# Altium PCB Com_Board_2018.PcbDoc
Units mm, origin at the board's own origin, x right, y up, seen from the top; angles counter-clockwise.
Board outline 97.2 x 100.86 mm, 2 copper layers (Top Layer, Bottom Layer), stack 1.57 mm thick; 18 components, 16 nets, 138 pads, 0 vias.
Unrouted connection lines stored in the file: 5.
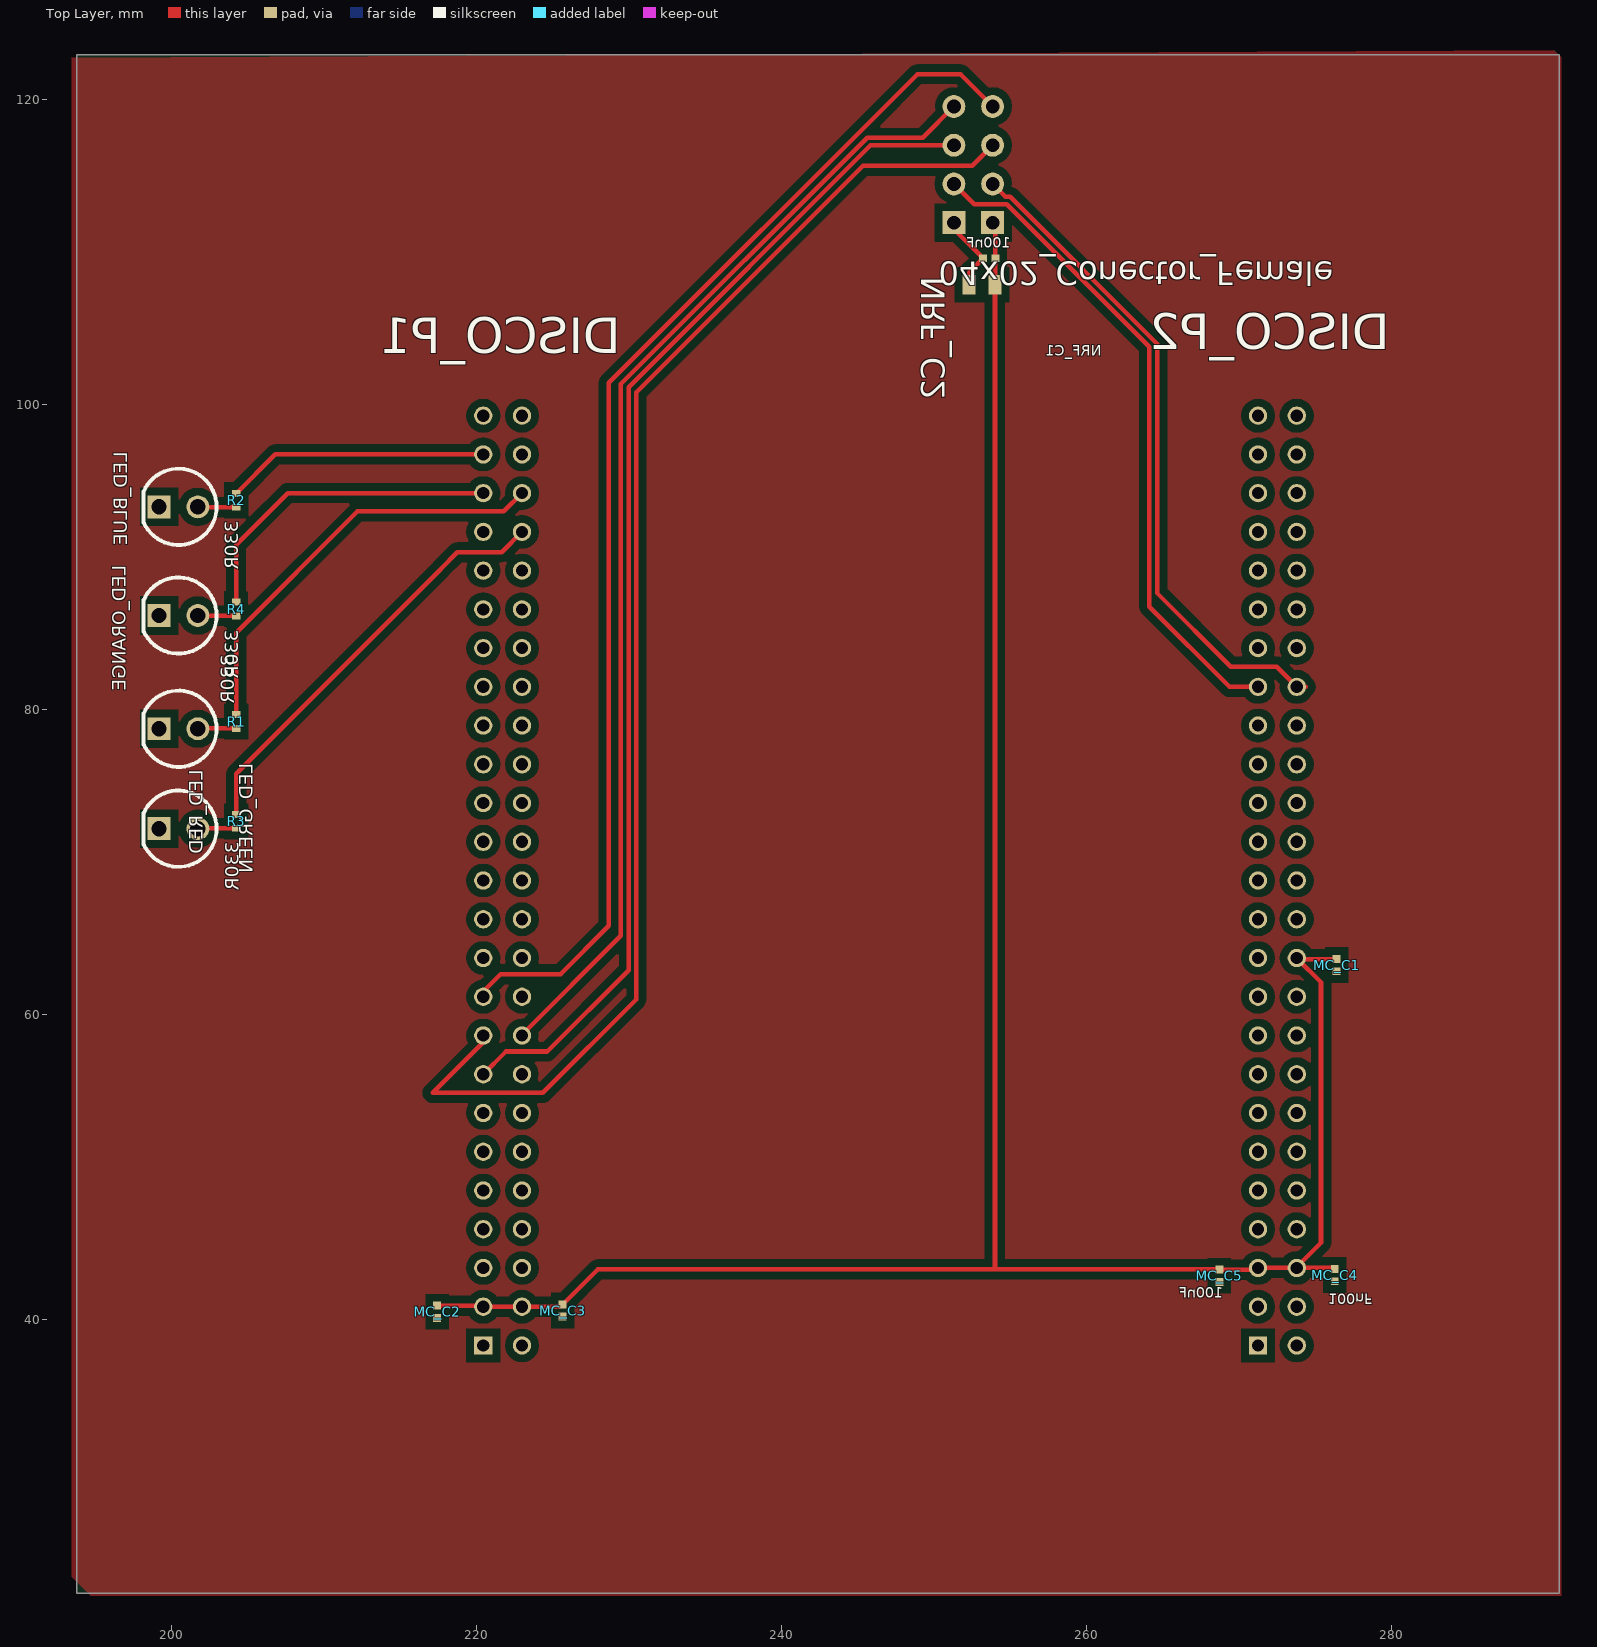
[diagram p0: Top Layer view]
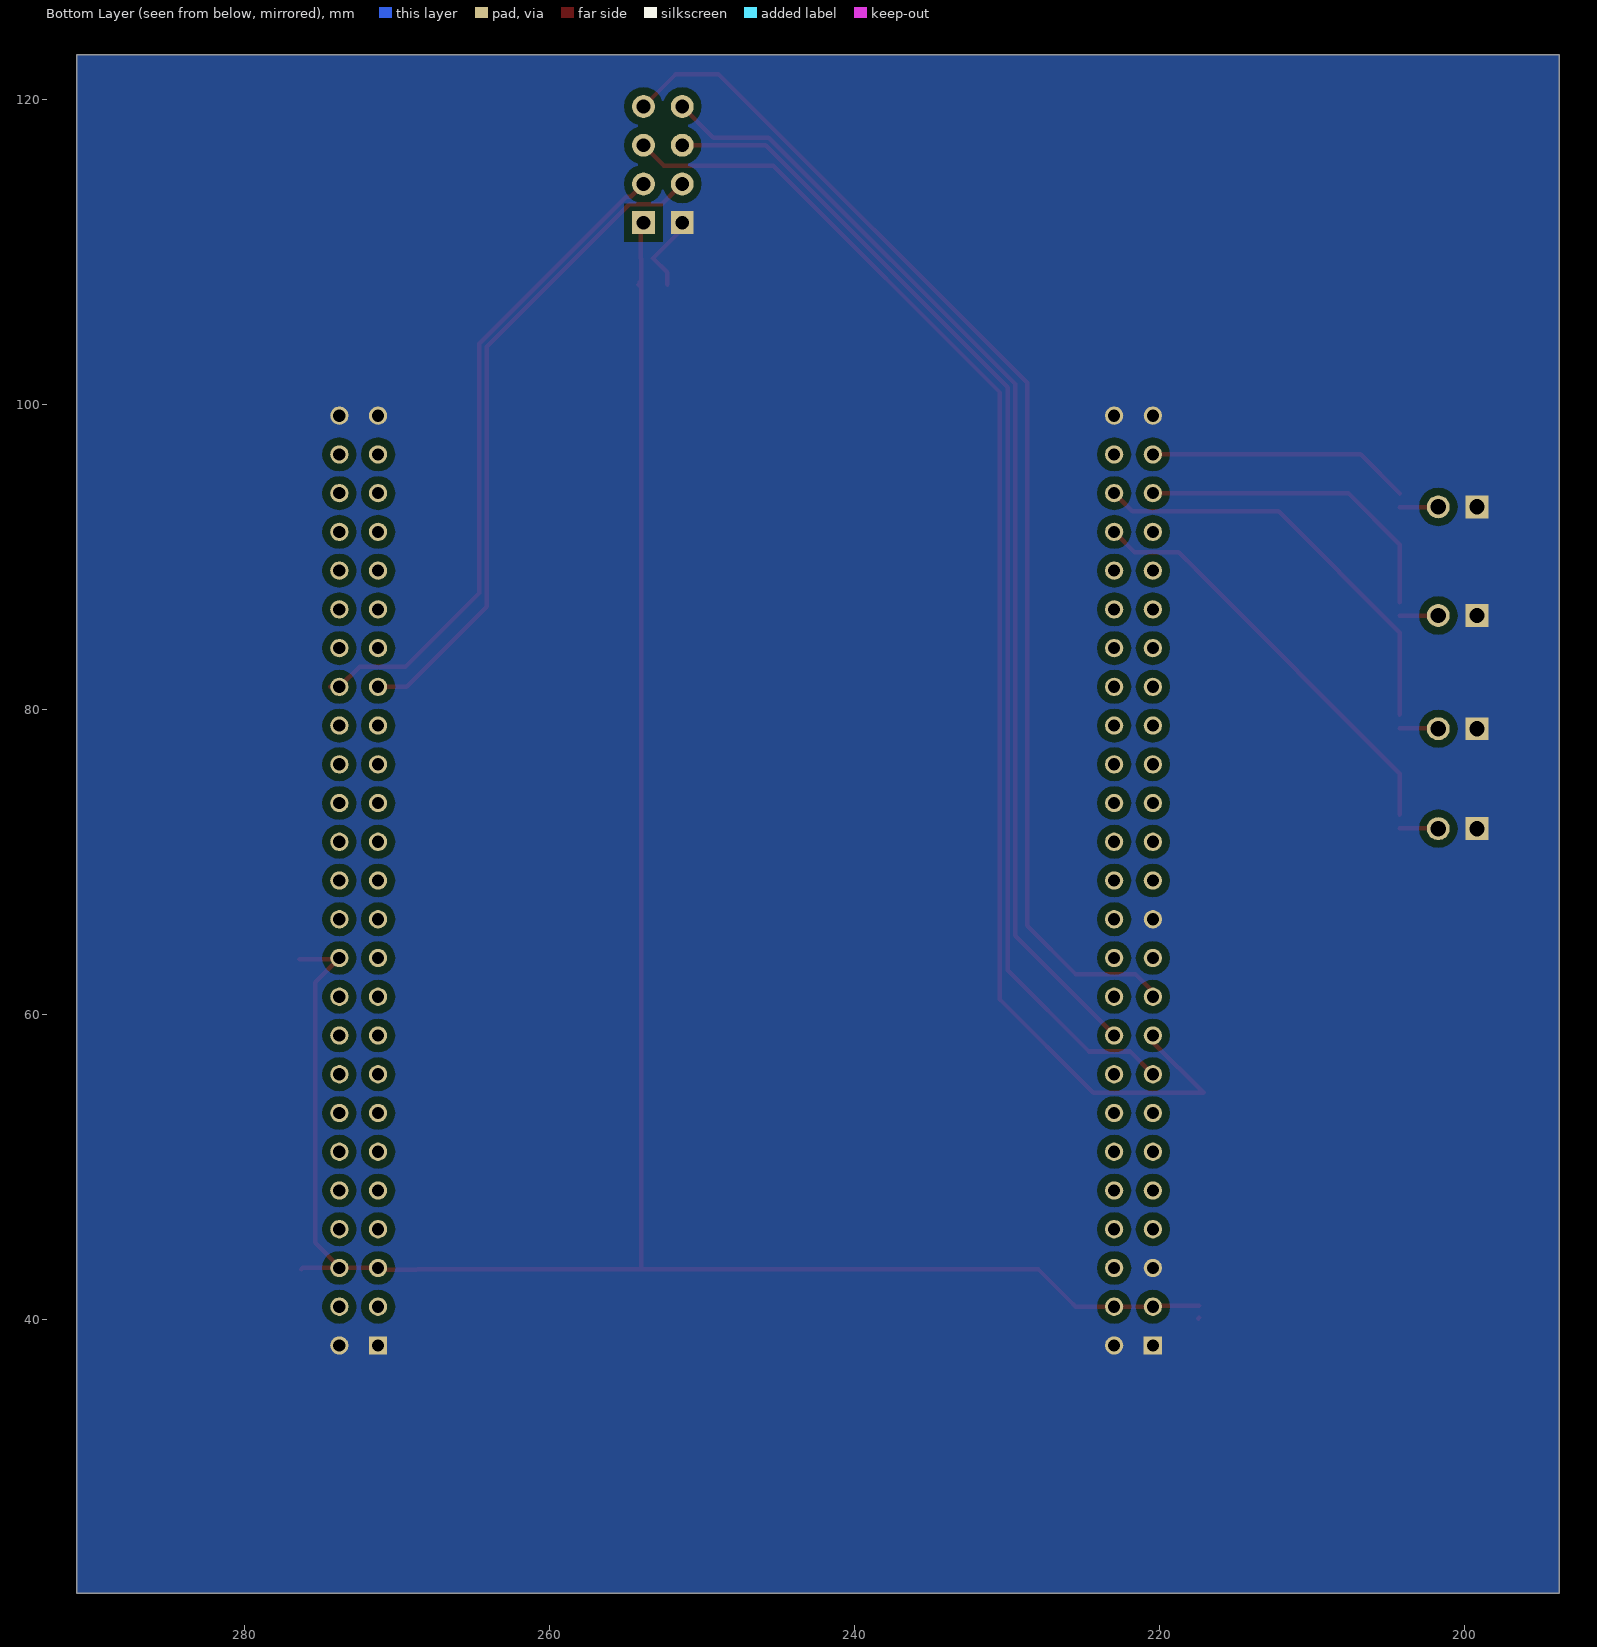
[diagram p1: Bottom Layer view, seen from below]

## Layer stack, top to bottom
Top Solder: solder mask 0.01, Solder Resist, Dk 3.5
Top Layer: signal copper 0.035
Dielectric 1: dielectric 1.5, FR-4, Dk 4.8
Bottom Layer: signal copper 0.035
Bottom Solder: solder mask 0.01, Solder Resist, Dk 3.5

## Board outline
193.775,122.937 193.775,22.075 290.975,22.075 290.975,122.937

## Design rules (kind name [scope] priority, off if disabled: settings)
Clearance Clearance_1 [All] p1: gap=0.3 ignorepadtopadclearanceinfootprint=FALSE except(0: Arc-Hole Track-Hole SMDPad-Hole THPad-Hole Via-Hole Fill-Hole Poly-Hole Region-Hole Text-Hole; 0.15: SMDPad-SMDPad; 0.2: Track-Track Track-SMDPad; 0.5: Arc-Poly Track-Poly SMDPad-Poly THPad-Poly Via-Poly Fill-Poly Poly-Poly Poly-Region Poly-Text)
HoleSize [All] p1: absolutevalues=TRUE maxlimit=10 minlimit=0.025 maxpercent=80.000 minpercent=20.000
MinimumSolderMaskSliver [All] p1 off: minsoldermaskwidth=0.2
PlaneConnect [All] p1: planeconnectstyle=Direct reliefexpansion=0.508 reliefentries=4 reliefconductorwidth=0.254 reliefairgap=0.254
PolygonConnect PolygonConnect_3 [InNet('GND')] p1: connectstyle=Direct reliefconductorwidth=0.254 reliefentries=4 polygonreliefangle="90 Angle" airgapwidth=0.254
PolygonConnect PolygonConnect_1 [InNetClass('DIRECT')] p2: connectstyle=Direct reliefconductorwidth=0.508 reliefentries=4 polygonreliefangle="90 Angle" airgapwidth=0.254
PolygonConnect PolygonConnect_2 [IsVia] p3: connectstyle=Direct reliefconductorwidth=0.254 reliefentries=4 polygonreliefangle="90 Angle" airgapwidth=0.254
PolygonConnect [All] p4: connectstyle=Direct reliefconductorwidth=0.3 reliefentries=4 polygonreliefangle="90 Angle" airgapwidth=0.254
RoutingVias [All] p1: holewidth=0.7 width=1 viastyle="Through Hole" minholewidth=0.5 minwidth=0.7 maxholewidth=6 maxwidth=6
SilkToSilkClearance [All] p1 off: silktosilkclearance=0.254
SilkToSolderMaskClearance [IsPad] p1 off: minsilkscreentomaskgap=0.254 clearancetoexposedcopper=TRUE
SolderMaskExpansion [All] p1: expansion=0.102
Width [All] p1: maxlimit=1.016 minlimit=0.2 preferedwidth=0.3
25 further rules are at their usual default settings.

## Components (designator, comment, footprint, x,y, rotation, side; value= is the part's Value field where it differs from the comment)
04x02_Conector_Female "PPPC042LFBN-RC" 04x02_Conector_Female 252.55,115.742 r270 top
DISCO_P1 "SFH11-PBPC-D25-ST-BK" 25x02_Conector_Female#1 221.693,68.799 r90 top locked
DISCO_P2 "SFH11-PBPC-D25-ST-BK" 25x02_Conector_Female#2 272.493,68.799 r90 top locked
LED_BLUE "LED" LED-5MM-PCB 200.44,93.3 r180 top
LED_GREEN "LED" LED-5MM-PCB 200.44,72.2 r180 top
LED_ORANGE "LED" LED-5MM-PCB 200.44,86.175 r180 top
LED_RED "LED" LED-5MM-PCB 200.44,78.75 r180 top
MC_C1 "100nF" 0402-CAP 276.375,63.25 r90 top value=100n
MC_C2 "100nF" 0402-CAP 217.4,40.525 r90 top value=100n
MC_C3 "100nF" 0402-CAP 225.63,40.605 r270 top value=100n
MC_C4 "100nF" 0402-CAP 276.25,42.925 r90 top value=100n
MC_C5 "100nF" 0402-CAP 268.683,42.891 r90 top value=100n
NRF_C1 "100nF" 0402-CAP 253.6,109.6 r180 top value=100n
NRF_C2 "10uF" 0805-CAP 253.125,107.867 r180 top
R1 "330R" 0402-RES-HD 204.225,79.225 r270 top value=330
R2 "330R" 0402-RES-HD 204.225,93.725 r270 top value=330
R3 "330R" 0402-RES-HD 204.225,72.675 r270 top value=330
R4 "330R" 0402-RES-HD 204.225,86.6 r270 top value=330

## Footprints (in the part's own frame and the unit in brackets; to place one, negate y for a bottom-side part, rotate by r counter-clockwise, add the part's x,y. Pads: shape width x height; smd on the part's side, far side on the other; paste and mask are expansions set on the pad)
04x02_Conector_Female [mm] "PPPC042LFBN-RC"
  round 1.5 hole 0.9: 0(-3.81,-1.27) 1(-1.27,-1.27) 2(1.27,-1.27) 4(-3.81,1.27) 5(-1.27,1.27) 6(1.27,1.27)
  rect 1.5x1.5 hole 0.9: 3(3.81,-1.27) 7(3.81,1.27)
  body extent -5.3,-2.53 5.36,2.55, height 150.38
25x02_Conector_Female#1 [mil] "SFH11-PBPC-D25-ST-BK"
  rect 47.25x47.25 hole 31.5: 1(-1200,50)
  round 47.25 hole 31.5: 2(-1200,-50) 3(-1100,50) 4(-1100,-50) 5(-1000,50) 6(-1000,-50) 7(-900,50) 8(-900,-50) 9(-800,50) 10(-800,-50) 11(-700,50) 12(-700,-50) 13(-600,50) 14(-600,-50) 15(-500,50) 16(-500,-50) 17(-400,50) 18(-400,-50) 19(-300,50) 20(-300,-50) 21(-200,50) 22(-200,-50) 23(-100,50) 24(-100,-50) 26(0,-50) 27(100,50) 28(100,-50) 29(200,50) 30(200,-50) 31(300,50) 32(300,-50) 33(400,50) 34(400,-50) 35(500,50) 36(500,-50) 37(600,50) 38(600,-50) 39(700,50) 40(700,-50) 41(800,50) 42(800,-50) 43(900,50) 44(900,-50) 45(1000,50) 46(1000,-50) 47(1100,50) 48(1100,-50) 49(1200,50) 50(1200,-50)
  oval 47.25x47.24 hole 31.5: 25(0,50)
  body extent -1350,-76 1350,161, height 333
25x02_Conector_Female#2 [mil] "SFH11-PBPC-D25-ST-BK"
  rect 47.25x47.25 hole 31.5: 1(-1200,50)
  round 47.25 hole 31.5: 2(-1200,-50) 3(-1100,50) 4(-1100,-50) 5(-1000,50) 6(-1000,-50) 7(-900,50) 8(-900,-50) 9(-800,50) 10(-800,-50) 11(-700,50) 12(-700,-50) 13(-600,50) 14(-600,-50) 15(-500,50) 16(-500,-50) 17(-400,50) 18(-400,-50) 19(-300,50) 20(-300,-50) 21(-200,50) 22(-200,-50) 23(-100,50) 24(-100,-50) 25(0,50) 26(0,-50) 27(100,50) 28(100,-50) 29(200,50) 30(200,-50) 31(300,50) 32(300,-50) 33(400,50) 34(400,-50) 35(500,50) 36(500,-50) 37(600,50) 38(600,-50) 39(700,50) 40(700,-50) 41(800,50) 42(800,-50) 43(900,50) 44(900,-50) 45(1000,50) 46(1000,-50) 47(1100,50) 48(1100,-50) 49(1200,50) 50(1200,-50)
  body extent -1350,-76 1350,161, height 333
0402-CAP [mm] "Chip Capacitor, Body 1.0x0.5mm, Height 0.6mm, IPC Medium Density"
  rect 0.52x0.52 smd: 1(-0.4,0) 2(0.4,0)
  body extent -0.55,-0.3 0.55,0.3, height 0.33
0402-RES-HD [mm] "Chip Resistor, Body 1.0x0.5mm, IPC High Density"
  rect 0.45x0.55 smd: 1(-0.45,0) 2(0.45,0)
  body extent -0.52,-0.28 0.53,0.27, height 0.4
0805-CAP [mm] "Chip Resistor, Body 2.0x1.3mm, IPC High Density"
  rect 0.85x1.3 smd: 1(-0.85,0) 2(0.85,0)
  body extent -1.1,-0.68 1.1,0.67, height 0.7
LED-5MM-PCB [mm]
  rect 1.5x1.5 hole 1: 1(1.27,0)
  round 1.5 hole 1: 2(-1.27,0)
  silkscreen extent -2.5,-2.5 2.28,2.5, body extent -2.98,-3.01 2.44,3.01, height 8.59

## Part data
04x02_Conector_Female: library part 04x02_Conector_Female, "8 Position Header Connector 0.100\" (2.54mm) Through Hole Gold"
DISCO_P1 DISCO_P2: library part 25x02_Conector_Female, "50 Position Header Connector 0.100\" (2.54mm) Through Hole Gold"
LED_BLUE LED_GREEN LED_ORANGE LED_RED: library part LED-5MM-3, "LED 5MM PTH"
MC_C1 MC_C2 MC_C3 MC_C4 MC_C5 NRF_C1: library part CC0402-100nF-A.12, "CAP CER 0.1UF 10V 20% X5R 0402", Part No=VJ0402V104ZXQPBC
NRF_C2: library part CC0806-10uF-25V-1, "CAP CER 10UF 25V X5R 0805", Part No=GRM21BR61E106KA73L
R1 R2 R3 R4: library part R0402-330R-7, "RES 330 OHM 1/10W 1% 0402 SMD", Part No=ERJ-2RKF3300X

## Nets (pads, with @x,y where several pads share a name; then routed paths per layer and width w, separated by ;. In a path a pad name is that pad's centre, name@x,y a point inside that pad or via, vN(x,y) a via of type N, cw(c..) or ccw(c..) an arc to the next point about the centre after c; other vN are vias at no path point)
GND: 04x02_Conector_Female.3 DISCO_P1.1 DISCO_P1.2 DISCO_P1.5 DISCO_P1.23 DISCO_P1.49 DISCO_P1.50 DISCO_P2.1 DISCO_P2.2 DISCO_P2.49 DISCO_P2.50 LED_BLUE.1 LED_GREEN.1 LED_ORANGE.1 LED_RED.1 MC_C1.1 MC_C2.1 MC_C3.2 MC_C4.1 MC_C5.1 NRF_C1.2 NRF_C2.2 | length 5.3
  Top Layer w0.3: MC_C2.1 MC_C2.1@217.45,40.075 ; 04x02_Conector_Female.3 251.28,111.52 NRF_C1.2 252.275,108.675 NRF_C2.2
LED_B: DISCO_P1.47 R2.1 | length 17.3
  Top Layer w0.3: R2.1 206.789,96.739 DISCO_P1.47
LED_G: DISCO_P1.44 R3.1 | length 28
  Top Layer w0.3: R3.1 204.225,75.8 217.625,89.2 217.625,89.225 218.725,90.325 221.629,90.325 DISCO_P1.44
LED_O: DISCO_P1.45 R4.1 | length 21.4
  Top Layer w0.3: R4.1 204.225,90.825 207.599,94.199 DISCO_P1.45
LED_R: DISCO_P1.46 R1.1 | length 27.9
  Top Layer w0.3: R1.1 204.225,85.05 212.175,93 221.764,93 DISCO_P1.46
NetLED_BLUE_2: LED_BLUE.2 R2.2 | length 2.4
  Top Layer w0.3: LED_BLUE.2@201.81,93.275 R2.2
NetLED_GREEN_2: LED_GREEN.2 R3.2 | length 2.3
  Top Layer w0.3: LED_GREEN.2@201.96,72.225 R3.2
NetLED_ORANGE_2: LED_ORANGE.2 R4.2 | length 2.5
  Top Layer w0.3: LED_ORANGE.2@201.735,86.15 R4.2
NetLED_RED_2: LED_RED.2 R1.2 | length 2.5
  Top Layer w0.3: LED_RED.2@201.735,78.775 R1.2
NRF_CE: 04x02_Conector_Female.2 DISCO_P2.35 | length 43.6
  Top Layer w0.3: 04x02_Conector_Female.2 252.62,113.132 254.756,113.132 264.1,103.788 264.1,86.75 269.351,81.499 DISCO_P2.35
NRF_CS#: 04x02_Conector_Female.6 DISCO_P2.36 | length 43.8
  Top Layer w0.3: 04x02_Conector_Female.6 254.66,113.632 254.964,113.632 264.6,103.995 264.6,87.65 269.425,82.825 272.437,82.825 DISCO_P2.36 DISCO_P2.36@274.349,81.499
NRF_IRQ: 04x02_Conector_Female.4 DISCO_P1.19 | length 80.4
  Top Layer w0.3: DISCO_P1.19 220.423,61.523 221.568,62.668 225.493,62.668 228.65,65.825 228.65,101.425 248.875,121.65 251.722,121.65 04x02_Conector_Female.4
SPI1_MISO: 04x02_Conector_Female.0 DISCO_P1.18 | length 74.9
  Top Layer w0.3: DISCO_P1.18@223.024,58.7 DISCO_P1.18 222.963,58.688 229.45,65.175 229.45,101.357 245.605,117.512 249.24,117.512 04x02_Conector_Female.0
SPI1_MOSI: 04x02_Conector_Female.5 DISCO_P1.17 | length 91
  Top Layer w0.3: DISCO_P1.17 220.423,58.198 217.1,54.875 224.325,54.875 230.45,61 230.45,100.8 245.322,115.672 252.48,115.672 04x02_Conector_Female.5 04x02_Conector_Female.5@253.82,117.13
SPI1_SCK: 04x02_Conector_Female.1 DISCO_P1.15 | length 78.5
  Top Layer w0.3: DISCO_P1.15 221.913,57.588 224.613,57.588 229.95,62.925 229.95,101.15 245.812,117.012 04x02_Conector_Female.1
VCC: 04x02_Conector_Female.7 DISCO_P1.3 DISCO_P1.4 DISCO_P2.5 DISCO_P2.6 DISCO_P2.22 MC_C1.2 MC_C2.2 MC_C3.1 MC_C4.2 MC_C5.2 NRF_C1.1 NRF_C2.1 | length 156.2
  Top Layer w0.3: MC_C2.2 220.357,40.925 DISCO_P1.3 DISCO_P1.4 225.484,40.859 MC_C3.1 227.925,43.3 256.675,43.3 256.7,43.325 ; 04x02_Conector_Female.7@253.588,111.7 04x02_Conector_Female.7 254,111.752 NRF_C1.1 253.975,109.575 NRF_C2.1 253.975,43.325 256.7,43.325 ; NRF_C2.1@254,107.717 NRF_C2.1@254.15,107.867 ; NRF_C2.1@254,108.117 NRF_C2.1@254.075,108.042 ; DISCO_P2.22 DISCO_P2.22@273.832,63.65 ; MC_C4.2 276.176,43.399 DISCO_P2.6 ; MC_C1.2 DISCO_P2.22@273.832,63.65 ; 256.7,43.325 268.649,43.325 MC_C5.2 271.115,43.291 DISCO_P2.5 DISCO_P2.6 ; DISCO_P2.6 273.763,43.463 275.35,45.05 275.35,62.132 DISCO_P2.22@273.832,63.65
pads on no net: DISCO_P1.6 DISCO_P1.7 DISCO_P1.8 DISCO_P1.9 DISCO_P1.10 DISCO_P1.11 DISCO_P1.12 DISCO_P1.13 DISCO_P1.14 DISCO_P1.16 DISCO_P1.20 DISCO_P1.21 DISCO_P1.22 DISCO_P1.24 DISCO_P1.25 DISCO_P1.26 DISCO_P1.27 DISCO_P1.28 DISCO_P1.29 DISCO_P1.30 DISCO_P1.31 DISCO_P1.32 DISCO_P1.33 DISCO_P1.34 DISCO_P1.35 DISCO_P1.36 DISCO_P1.37 DISCO_P1.38 DISCO_P1.39 DISCO_P1.40 DISCO_P1.41 DISCO_P1.42 DISCO_P1.43 DISCO_P1.48 DISCO_P2.3 DISCO_P2.4 DISCO_P2.7 DISCO_P2.8 DISCO_P2.9 DISCO_P2.10 DISCO_P2.11 DISCO_P2.12 DISCO_P2.13 DISCO_P2.14 DISCO_P2.15 DISCO_P2.16 DISCO_P2.17 DISCO_P2.18 DISCO_P2.19 DISCO_P2.20 DISCO_P2.21 DISCO_P2.23 DISCO_P2.24 DISCO_P2.25 DISCO_P2.26 DISCO_P2.27 DISCO_P2.28 DISCO_P2.29 DISCO_P2.30 DISCO_P2.31 DISCO_P2.32 DISCO_P2.33 DISCO_P2.34 DISCO_P2.37 DISCO_P2.38 DISCO_P2.39 DISCO_P2.40 DISCO_P2.41 DISCO_P2.42 DISCO_P2.43 DISCO_P2.44 DISCO_P2.45 DISCO_P2.46 DISCO_P2.47 DISCO_P2.48

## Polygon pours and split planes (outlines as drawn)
no net on Top Layer (solid, pour order 167): 193.45,122.75 193.45,23.15 194.7,21.9 291.1,21.9 291.1,122.775 290.625,123.25
no net on Top Layer (solid, pour order 165): 193.2,122.5
no net on Top Layer "Top Layer-No Net 1" (solid, pour order 133): 320.1,155.1
GND on Bottom Layer "Top Layer-No Net2" (solid, pour order 146): 193.775,122.937 193.775,22.075 290.975,22.075 290.975,122.937

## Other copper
Top Layer:
  region: -133.25,79.25

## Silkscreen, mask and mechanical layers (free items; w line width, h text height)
Mechanical 1:
  lines w0.5: 290.975,122.22 290.975,22.075 ; 193.775,22.075 290.975,22.075 ; 193.775,22.075 193.775,122.937 ; 193.775,22.075 290.975,22.075 ; 193.775,22.075 193.775,122.937 ; 193.775,122.937 290.975,122.937 290.975,22.075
